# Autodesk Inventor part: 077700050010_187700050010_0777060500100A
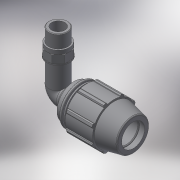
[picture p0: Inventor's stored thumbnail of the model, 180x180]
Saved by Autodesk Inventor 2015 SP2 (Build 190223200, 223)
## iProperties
Created: 2017-02
Part Number: 077700050010_187700050010_0777060500100A
Material: Generic
Description: PLASSON 90° ELBOW MALE WITH INTEGRAL BRASS THREAD 50-1"
Document SubType Name: Modeling
Designer: KIM
Mass: 174.249 g
Surface Area: 431.906 cm^2
Volume: 174.249 cm^3
Density: 1 g/cm^3
Appearance: Default
Author: KIM
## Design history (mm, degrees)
derived "07770.ipt"
feature "Solid1::07770.ipt"
tag "TaggingFeature1"
body "Solid1"
other parameters: "d4" = 12, "d5" = 36, "d7" = 96, "d9" = 20.57143, "d11" = 4.8, "d13" = 120 deg, "d15" = 12 deg, "d16" = 83.52, "d18" = 2.5, "d19" = 35 deg, "d20" = 17.5 deg, "d21" = 89.28, "d23" = 0, "d25" = 360 deg, "d27" = 1.92, "d33" = 1, "d42" = 53.28, "d43" = 2.88, "d46" = 1.5, "d51" = 144, "d68" = 9.6, "d72" = 94, "d73" = 33.249, "d75" = 38.23635, "d76" = 23.2743, "d79" = 13.2996, "d80" = 0.99747, "d83" = 0, "d84" = 0, "d91" = 72, "d93" = 93, "d94" = 33.249, "d95" = 23.2743, "d96" = 9.6, "d97" = 50 deg, "d98" = 2.4, "d99" = 81.0144, "d100" = 2.4, "d101" = 2.4, "d105" = 2, "d106" = 39.8988, "d108" = 12, "d109" = 0, "E_" = 96, "A_" = 144, "l_" = 93, "A_1" = 94, "R_" = 33.249
